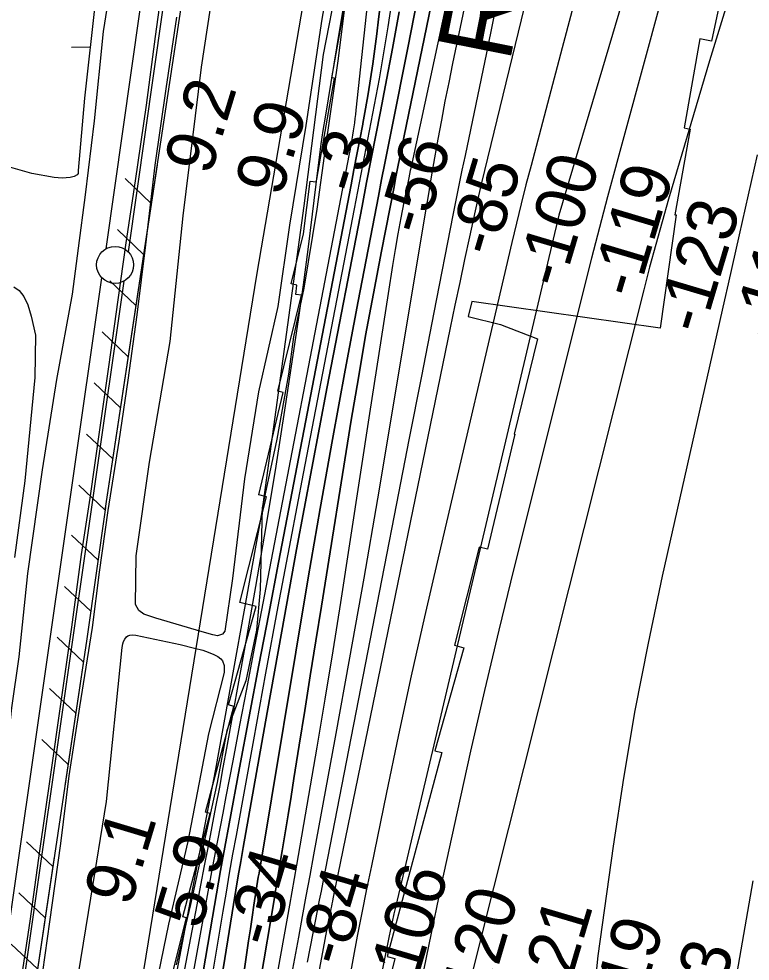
# Model space of a CAD drawing. Extents: x 3683613 to 3738215, y 469626 to 495384.
# Drawn here: x 3701179 to 3702169, y 479520 to 480796 of the extents above; entities that cross this region are included whole.
import ezdxf

# ---------------------------------------------------------------- set-up
doc = ezdxf.new("R2010")
doc.units = 0
for name, color, linetype in [('V-FLOD-BASE', 7, 'Continuous'), ('V-LEVE-TOET', 7, 'Continuous'), ('V-RIVR-EDGE', 7, 'Continuous'), ('V-RIVR-RANG', 7, 'Continuous'), ('V-RRAP-FSHR', 7, 'Continuous'), ('V-RRAP-RVMT', 7, 'Continuous'), ('V-RRAP-RVMT-IDEN', 7, 'Continuous'), ('V-SITE-VEGE', 7, 'Continuous'), ('V-SURV-LINE', 7, 'Continuous'), ('V-TOPO-DPTH', 7, 'Continuous'), ('V-TOPO-MAJR', 7, 'Continuous'), ('V-TOPO-MINR', 7, 'Continuous'), ('V-TOPO-WATR', 7, 'Continuous'), ('V-WETL-SWMP', 7, 'Continuous')]:
    doc.layers.add(name, color=color, linetype=linetype)

msp = doc.modelspace()

# ---------------------------------------------------------------- linework, layer by layer
at = {"layer": 'V-FLOD-BASE'}
msp.add_lwpolyline([(3701180.2, 479477.9), (3701194.5, 479573.7), (3701207.9, 479669), (3701222, 479769.3), (3701236.5, 479870.7), (3701251.2, 479971.9), (3701264, 480070), (3701275.9, 480146.6), (3701288.8, 480238.8), (3701301.1, 480324.2), (3701313.5, 480415.2), (3701324.6, 480492.1), (3701337, 480576.1), (3701351.9, 480678.7), (3701364.2, 480771.4), (3701376.3, 480860.7)], dxfattribs=at)
at = {"layer": 'V-LEVE-TOET'}
for points in [[(3701121.3, 479485), (3701137.7, 479604.2), (3701148.4, 479692.7), (3701157.7, 479758.9), (3701164.1, 479808), (3701169.8, 479862.6), (3701179.6, 479931.6), (3701191.4, 480044.6), (3701211.5, 480184.9), (3701230.7, 480307), (3701252, 480422.6), (3701260.2, 480485.2), (3701269.6, 480557), (3701281.8, 480657.3), (3701294, 480778.4), (3701313.2, 480900.7)], [(3701208.6, 479482.7), (3701221.2, 479572.9), (3701235.9, 479679.1), (3701247.6, 479770.7), (3701261.9, 479864), (3701278.8, 479971.6), (3701288.5, 480046.3), (3701300, 480129.7), (3701315.1, 480223.9), (3701327.3, 480306.4), (3701339.3, 480394.6), (3701351, 480489.3), (3701363.7, 480597.2), (3701378.7, 480700.6), (3701393.2, 480797.6)]]:
    msp.add_lwpolyline(points, dxfattribs=at)
at = {"layer": 'V-RIVR-EDGE'}
msp.add_lwpolyline([(3701622, 480825.2), (3701610.9, 480738.8), (3701594.4, 480623), (3701582.8, 480537.8), (3701565.1, 480431), (3701551.2, 480365), (3701544.4, 480314.5), (3701528.6, 480226.3), (3701508.6, 480133.3), (3701505.9, 480022.9), (3701501, 479967.7), (3701486.4, 479899.3), (3701461, 479832.1), (3701447.6, 479761.3), (3701432.4, 479691.7), (3701411.8, 479596.3), (3701392.4, 479514.7)], dxfattribs=at)
at = {"layer": 'V-RRAP-FSHR'}
for p, q in [((3701358.6, 480545.7), (3701323.2, 480579.4)), ((3701348.1, 480476.5), (3701312.8, 480510.1)), ((3701337.7, 480407.3), (3701302.3, 480440.9)), ((3701327.2, 480338), (3701291.9, 480371.7)), ((3701316.8, 480268.8), (3701281.4, 480302.5)), ((3701306.3, 480199.6), (3701270.9, 480233.3)), ((3701295.9, 480130.4), (3701260.5, 480164.1)), ((3701286.4, 480063.1), (3701250.7, 480096.4)), ((3701276.7, 479993.7), (3701240.9, 480027.1)), ((3701266.6, 479924.5), (3701231.2, 479958.1)), ((3701256.2, 479855.2), (3701220.8, 479888.9)), ((3701245.9, 479786), (3701210.5, 479819.6)), ((3701225.1, 479647.6), (3701189.7, 479681.2)), ((3701214.7, 479578.3), (3701179.3, 479612)), ((3701204.4, 479509.1), (3701169, 479542.7))]:
    msp.add_line(p, q, dxfattribs=at)
for points in [[(3701810.1, 483305.3), (3701737.4, 482845), (3701622, 482434.4), (3701596.4, 482302.9), (3701555, 481995.8), (3701532, 481804.5), (3701509, 481621.6), (3701469.4, 481255.9), (3701435.2, 481053.2), (3701296.3, 480133.1)], [(3701694.6, 481579.9), (3701501.3, 480451), (3701316.1, 479309.5), (3701244.1, 478830.2), (3701209.8, 478527.4), (3701127.5, 478317.7), (3700975.4, 478064.7), (3700849.2, 477767.3), (3700795.1, 477596.8), (3700754.6, 477321.3), (3700601.5, 476916.1), (3700241, 476175.5)], [(3701366.5, 480597.9), (3701296.3, 480133.1), (3701296.4, 480134), (3701271.4, 479956.2), (3701241.5, 479757.2)], [(3701296.4, 480134), (3701271.4, 479956.2), (3701142.6, 479096.9), (3701054.7, 478586.5), (3700925.4, 478175.9), (3700775.3, 477540.8), (3700732.4, 477433.8), (3700429.5, 476944.1)], [(3701227, 479660.3), (3701142.6, 479096.9), (3701127.6, 479010)]]:
    msp.add_lwpolyline(points, dxfattribs=at)
at = {"layer": 'V-RRAP-RVMT'}
for p, q in [((3702148.7, 480915.8), (3702116.7, 480765.2)), ((3701603, 480715.7), (3701630, 480868.7)), ((3702100.8, 480768.5), (3702079.6, 480647.9)), ((3702116.7, 480765.2), (3702100.8, 480768.5)), ((3701582.6, 480578.5), (3701606.7, 480715)), ((3701606.7, 480715), (3701603, 480715.7)), ((3702087.8, 480646.3), (3702067.3, 480530.2)), ((3702079.6, 480647.9), (3702087.8, 480646.3)), ((3701564.6, 480504.4), (3701573.7, 480575.7)), ((3701573.7, 480575.7), (3701581.8, 480574.7)), ((3701581.8, 480574.7), (3701582.8, 480578.4)), ((3701582.8, 480578.4), (3701582.6, 480578.5)), ((3702069.1, 480530), (3702047.5, 480376.8)), ((3702067.3, 480530.2), (3702069.1, 480530)), ((3701548, 480436.8), (3701564.6, 480504.4)), ((3701555.7, 480434.9), (3701548, 480436.8)), ((3701554.1, 480422.4), (3701555.7, 480434.9)), ((3701561.7, 480421.4), (3701554.1, 480422.4)), ((3701529.8, 480291.4), (3701561.7, 480421.4)), ((3701792.4, 480412.7), (3701787.5, 480392.5)), ((3702047.5, 480376.8), (3701792.4, 480412.7)), ((3701787.5, 480392.5), (3701831.4, 480381.8)), ((3701831.4, 480381.8), (3701881.2, 480362.1)), ((3701881.2, 480362.1), (3701849.7, 480233.3)), ((3701504.1, 480150.8), (3701537, 480289.7)), ((3701537, 480289.7), (3701529.8, 480291.4)), ((3701850.5, 480233.1), (3701813.7, 480077.6)), ((3701849.7, 480233.3), (3701850.5, 480233.1)), ((3701478.6, 480005.2), (3701514.7, 480148.2)), ((3701514.7, 480148.2), (3701504.1, 480150.8)), ((3701802.4, 480080.2), (3701768.8, 479947.4)), ((3701813.7, 480077.6), (3701802.4, 480080.2)), ((3701500.3, 479999.8), (3701478.6, 480005.2)), ((3701463, 479866.5), (3701500.3, 479999.8)), ((3701781.4, 479943.9), (3701742.4, 479804.6)), ((3701768.8, 479947.4), (3701781.4, 479943.9)), ((3701432, 479721.4), (3701470.1, 479864.5)), ((3701470.1, 479864.5), (3701463, 479866.5)), ((3701751.6, 479802.2), (3701710.4, 479647.3)), ((3701742.4, 479804.6), (3701751.6, 479802.2)), ((3701438.4, 479719.6), (3701432, 479721.4)), ((3701401.1, 479579.5), (3701438.4, 479719.6)), ((3701710.1, 479647.3), (3701677.7, 479525.7)), ((3701710.4, 479647.3), (3701710.1, 479647.3)), ((3701370.9, 479436.7), (3701406.1, 479578.1)), ((3701406.1, 479578.1), (3701401.1, 479579.5)), ((3701688.2, 479523.1), (3701652.2, 479379)), ((3701677.7, 479525.7), (3701688.2, 479523.1))]:
    msp.add_line(p, q, dxfattribs=at)
at = {"layer": 'V-SITE-VEGE'}
for points in [[(3701613.4, 480930.4), (3701589.5, 480795.3), (3701567.7, 480651.3), (3701545.4, 480516), (3701529.6, 480405.8), (3701503.7, 480290.5), (3701484.9, 480172.8), (3701468.5, 480037.8), (3701458, 479966.2), (3701455, 479962.3), (3701448.3, 479960), (3701441.9, 479961.3), (3701427.6, 479965.3), (3701364.8, 479984), (3701348.6, 479989.6), (3701341.8, 479994.3), (3701337, 480002.6), (3701338.1, 480068.2), (3701355.9, 480195.1), (3701384.2, 480358.7), (3701401.6, 480528.6), (3701426.6, 480729.9), (3701453.8, 480911.3)], [(3701253.2, 479461), (3701276.6, 479604.9), (3701298, 479735.7), (3701319.3, 479944.5), (3701320, 479949.1), (3701320.8, 479952.6), (3701322.6, 479955.7), (3701324.8, 479958.7), (3701326.7, 479960.1), (3701329.4, 479961.2), (3701332.6, 479961.5), (3701337.8, 479961), (3701397.8, 479948.2), (3701416.9, 479943.6), (3701428.1, 479940.7), (3701435.7, 479938.1), (3701443.1, 479934.9), (3701448.6, 479932.3), (3701452.7, 479929.1), (3701454.9, 479926.4), (3701457.1, 479919.9), (3701457, 479910.4), (3701435.8, 479827.2), (3701408, 479681.6), (3701381.8, 479569.8), (3701364.9, 479486.1)]]:
    msp.add_lwpolyline(points, dxfattribs=at)
at = {"layer": 'V-SURV-LINE'}
for points in [[(3701297.4, 480484.2), (3701560.1, 482333.7)], [(3701589.8, 482329.5), (3701327.1, 480480)], [(3701045.4, 478725.5), (3701291.8, 480444.7)], [(3701321.5, 480440.4), (3701075.1, 478721.3)]]:
    msp.add_lwpolyline(points, dxfattribs=at)
msp.add_circle((3701309.5, 480462.3), 25, dxfattribs=at)
at = {"layer": 'V-TOPO-DPTH'}
for points in [[(3701626.5, 480858.6), (3701613.2, 480781.3), (3701593.7, 480662.6), (3701590.8, 480644.5), (3701588.1, 480626.4), (3701585.7, 480608.3), (3701583.4, 480590.1), (3701576.2, 480530.9), (3701570.2, 480483.2), (3701563.9, 480435.4), (3701557.2, 480387.8), (3701550.2, 480340.2), (3701539.7, 480271.7), (3701526.9, 480189.9), (3701513.6, 480108.3), (3701499.7, 480026.7), (3701485.3, 479945.2), (3701460.5, 479808.1), (3701455.6, 479781.6), (3701450.7, 479755), (3701445.6, 479728.4), (3701440.5, 479701.9), (3701435.4, 479675.4), (3701430.2, 479648.8), (3701425.1, 479622.3), (3701420, 479595.8), (3701337.1, 479162.8)], [(3701484.3, 479505.9), (3701488, 479531.2), (3701490.3, 479547.2), (3701492.7, 479563.2), (3701495.1, 479579.2), (3701497.5, 479595.3), (3701500.7, 479615.7), (3701501.6, 479621.5), (3701502.5, 479627.3), (3701503.4, 479633.1), (3701504.4, 479638.9), (3701571.1, 480038.5), (3701587.1, 480132.3), (3701603.7, 480226.1), (3701620.9, 480319.8), (3701638.6, 480413.3), (3701666, 480555.3), (3701670.3, 480577.8), (3701674.7, 480600.3), (3701679.2, 480622.8), (3701683.6, 480645.3), (3701706.2, 480758.3), (3701721.5, 480837.4)], [(3701484.3, 479505.9), (3701488, 479531.2), (3701490.3, 479547.2), (3701492.7, 479563.2), (3701495.1, 479579.2), (3701497.5, 479595.3), (3701500.7, 479615.7), (3701501.6, 479621.5), (3701502.5, 479627.3), (3701503.4, 479633.1), (3701504.4, 479638.9), (3701571.1, 480038.5), (3701587.1, 480132.3), (3701603.7, 480226.1), (3701620.9, 480319.8), (3701638.6, 480413.3), (3701666, 480555.3), (3701670.3, 480577.8), (3701674.7, 480600.3), (3701679.2, 480622.8), (3701683.6, 480645.3), (3701706.2, 480758.3), (3701721.5, 480837.4)], [(3701668.6, 480815.7), (3701666.2, 480795.3), (3701663.7, 480775), (3701661, 480754.7), (3701658.2, 480734.4), (3701655.3, 480714.1), (3701652.1, 480693.9), (3701648.6, 480673.7), (3701644.8, 480653.6), (3701644.7, 480652.8), (3701640.7, 480632.2), (3701636.8, 480611.7), (3701632.8, 480591.2), (3701628.9, 480570.7), (3701530.8, 480059.6), (3701517.5, 479990.1), (3701504.3, 479920.5), (3701491.2, 479851), (3701478.1, 479781.4), (3701463.9, 479705.4), (3701458.1, 479673.8), (3701452.4, 479642.2), (3701446.8, 479610.6), (3701441.3, 479579), (3701419.2, 479449.7)], [(3701419.2, 479449.7), (3701441.3, 479579), (3701446.8, 479610.6), (3701452.4, 479642.2), (3701458.1, 479673.8), (3701463.9, 479705.4), (3701478.1, 479781.4), (3701491.2, 479851), (3701504.3, 479920.5), (3701517.5, 479990.1), (3701530.8, 480059.6), (3701628.9, 480570.7), (3701632.8, 480591.2), (3701636.8, 480611.7), (3701640.7, 480632.2), (3701644.7, 480652.8), (3701644.8, 480653.6), (3701648.6, 480673.7), (3701652.1, 480693.9), (3701655.3, 480714.1), (3701658.2, 480734.4), (3701661, 480754.7), (3701663.7, 480775), (3701666.2, 480795.3), (3701668.6, 480815.7)], [(3701449.2, 479467.3), (3701458, 479523.3), (3701469.9, 479596.5), (3701473, 479615.8), (3701476.3, 479635.1), (3701479.6, 479654.4), (3701483, 479673.7), (3701515.3, 479856.1), (3701535.1, 479966.5), (3701555.2, 480076.9), (3701575.9, 480187.2), (3701596.8, 480297.4), (3701643.8, 480541.9), (3701650, 480573.9), (3701656.2, 480605.9), (3701662.4, 480637.9), (3701668.7, 480669.9), (3701675.6, 480705.5), (3701685.1, 480755.3), (3701694, 480805.2)], [(3701694, 480805.2), (3701685.1, 480755.3), (3701675.6, 480705.5), (3701668.7, 480669.9), (3701662.4, 480637.9), (3701656.2, 480605.9), (3701650, 480573.9), (3701643.8, 480541.9), (3701596.8, 480297.4), (3701575.9, 480187.2), (3701555.2, 480076.9), (3701535.1, 479966.5), (3701515.3, 479856.1), (3701483, 479673.7), (3701479.6, 479654.4), (3701476.3, 479635.1), (3701473, 479615.8), (3701469.9, 479596.5), (3701458, 479523.3), (3701449.2, 479467.3)], [(3701737.4, 480814.5), (3701697.8, 480621.9), (3701695.1, 480608.4), (3701692.4, 480595), (3701689.7, 480581.6), (3701687.1, 480568.1), (3701670, 480480.9), (3701659.1, 480423.8), (3701648.7, 480366.7), (3701638.8, 480309.4), (3701629.3, 480252.1), (3701588.8, 480000.2), (3701581.3, 479953.1), (3701573.8, 479906.1), (3701566.3, 479859), (3701558.8, 479812), (3701551.7, 479766.9), (3701547.8, 479742.4), (3701543.8, 479717.9), (3701539.8, 479693.3), (3701535.7, 479668.8), (3701530, 479634.1), (3701528.8, 479626.9), (3701527.6, 479619.8), (3701526.4, 479612.7), (3701525.2, 479605.5), (3701467, 479261.5)], [(3701467, 479261.5), (3701525.2, 479605.5), (3701526.4, 479612.7), (3701527.6, 479619.8), (3701528.8, 479626.9), (3701530, 479634.1), (3701535.7, 479668.8), (3701539.8, 479693.3), (3701543.8, 479717.9), (3701547.8, 479742.4), (3701551.7, 479766.9), (3701558.8, 479812), (3701566.3, 479859), (3701573.8, 479906.1), (3701581.3, 479953.1), (3701588.8, 480000.2), (3701629.3, 480252.1), (3701638.8, 480309.4), (3701648.7, 480366.7), (3701659.1, 480423.8), (3701670, 480480.9), (3701687.1, 480568.1), (3701689.7, 480581.6), (3701692.4, 480595), (3701695.1, 480608.4), (3701697.8, 480621.9), (3701737.4, 480814.5)]]:
    msp.add_lwpolyline(points, dxfattribs=at)
at = {"layer": 'V-TOPO-MAJR'}
for points in [[(3702153.7, 481350.6), (3701910.1, 480529.5), (3701910.1, 480529.5)], [(3701800.4, 481014.8), (3701711.1, 480599.7), (3701710.1, 480594.8), (3701709.1, 480590), (3701708.1, 480585.1), (3701707.1, 480580.2), (3701700.5, 480547.3), (3701696.4, 480525.9), (3701692.4, 480504.4), (3701688.7, 480483), (3701685.2, 480461.5), (3701679.2, 480423.4), (3701672.9, 480382.8), (3701666.5, 480342.2), (3701660.2, 480301.6), (3701653.9, 480261), (3701614.5, 480005.2), (3701604.2, 479939.8), (3701593.6, 479874.5), (3701582.7, 479809.2), (3701571.5, 479743.9), (3701555, 479649.5), (3701551.8, 479631.5), (3701548.6, 479613.5), (3701545.5, 479595.5), (3701542.3, 479577.6), (3701513.3, 479415)], [(3701910.1, 480529.5), (3701689.4, 479594.3), (3701687, 479583.7), (3701684.6, 479573), (3701682.2, 479562.3), (3701680, 479551.6), (3701667.7, 479491.6)]]:
    msp.add_lwpolyline(points, dxfattribs=at)
at = {"layer": 'V-TOPO-MINR'}
for points in [[(3701942.1, 481135.9), (3701805.6, 480573.6), (3701804.2, 480567.7), (3701802.8, 480561.8), (3701801.5, 480555.9), (3701800.1, 480550), (3701789.3, 480500.3), (3701782.6, 480469.5), (3701776, 480438.7), (3701769.6, 480407.9), (3701763.2, 480377.1), (3701604.3, 479604.1), (3701603.6, 479600.7), (3701603, 479597.3), (3701602.3, 479594), (3701601.6, 479590.6), (3701598.1, 479573.1), (3701595.8, 479560.9), (3701593.4, 479548.8), (3701591.1, 479536.7), (3701588.9, 479524.5), (3701574.7, 479447.6)], [(3699911.1, 475180.8), (3700010.1, 475361), (3700100.2, 475592.8), (3700211, 475886.8), (3700368.1, 476293.1), (3700511.5, 476644.6), (3700757.8, 477156.6), (3700794.8, 477247.5), (3700948.6, 477732.3), (3701076.7, 478169.2), (3701195.6, 478587), (3701259.6, 478816.2), (3701288.9, 478956.9), (3701418.9, 479639), (3701445.8, 479779.7), (3701508.4, 480127.8), (3701565.5, 480542.5), (3701591.6, 480747.4), (3701650, 481045.5)], [(3702072.6, 480909.9), (3701976, 480554.5), (3701970.4, 480533.7), (3701965, 480513), (3701959.6, 480492.2), (3701954.3, 480471.4), (3701848.9, 480049.4), (3701828.9, 479967.7), (3701809.4, 479885.9), (3701790.7, 479803.9), (3701772.5, 479721.8), (3701751.1, 479622.9), (3701744.1, 479590.1), (3701737.2, 479557.3)], [(3701942.5, 480861.9), (3701914.8, 480756.2), (3701872.5, 480596.8), (3701865.7, 480570.8), (3701859.1, 480544.9), (3701852.7, 480518.8), (3701846.5, 480492.7), (3701746.8, 480065.7), (3701728.5, 479985.8), (3701710.5, 479905.9)], [(3701654, 480844.3), (3701635.5, 480671.7), (3701634.9, 480666.1), (3701634.2, 480660.5), (3701633.5, 480654.9), (3701632.8, 480649.3), (3701632, 480643.8), (3701631.1, 480638.2), (3701630.2, 480632.7), (3701629.2, 480627.1), (3701627.6, 480618.9), (3701627.2, 480616.8), (3701626.8, 480614.7), (3701626.4, 480612.7), (3701626, 480610.6), (3701496.5, 479936.1), (3701487.3, 479887.7), (3701478, 479839.3), (3701468.7, 479790.9), (3701459.5, 479742.5), (3701455.2, 479720.2), (3701448.1, 479682.9), (3701441.1, 479645.6), (3701434.2, 479608.3), (3701427.4, 479570.9), (3701382.4, 479322.7)], [(3701721.5, 480837.4), (3701706.2, 480758.3), (3701683.6, 480645.3), (3701679.2, 480622.8), (3701674.7, 480600.3), (3701670.3, 480577.8), (3701666, 480555.3), (3701638.6, 480413.3), (3701620.9, 480319.8), (3701603.7, 480226.1), (3701587.1, 480132.3), (3701571.1, 480038.5), (3701504.4, 479638.9), (3701503.4, 479633.1), (3701502.5, 479627.3), (3701501.6, 479621.5), (3701500.7, 479615.7), (3701497.5, 479595.3), (3701495.1, 479579.2), (3701492.7, 479563.2), (3701490.3, 479547.2), (3701488, 479531.2), (3701484.3, 479505.9)], [(3701830.4, 480839.3), (3701812.1, 480749.6), (3701783.2, 480610.6), (3701779, 480590.4), (3701774.9, 480570.2), (3701770.8, 480549.9), (3701766.8, 480529.7), (3701741, 480397.9), (3701724.2, 480311.8), (3701707.3, 480225.6), (3701690.5, 480139.5), (3701673.7, 480053.3), (3701590.6, 479626.6), (3701588.3, 479614.5), (3701585.9, 479602.4), (3701583.6, 479590.3), (3701581.2, 479578.2), (3701569.6, 479518.1)], [(3702144.8, 480839), (3702114.2, 480738.5), (3702058.7, 480551.2), (3702049.9, 480520.7), (3702041.3, 480490), (3702033.1, 480459.3), (3702025.1, 480428.5), (3701801.2, 479538.2), (3701622.5, 478819.7)], [(3701684.1, 480820.3), (3701678.7, 480784.9), (3701673, 480749.6), (3701666.8, 480714.3), (3701660.2, 480679.1), (3701653.4, 480643.9), (3701646.6, 480608.8), (3701639.8, 480573.6), (3701633, 480538.4), (3701564.2, 480179.9), (3701547, 480089.8), (3701530, 479999.7), (3701513.3, 479909.5), (3701496.7, 479819.3), (3701473.2, 479689.9), (3701468.6, 479664.4), (3701464.1, 479638.8), (3701459.7, 479613.1), (3701455.4, 479587.5), (3701438.7, 479487.2)], [(3701668.6, 480815.7), (3701666.2, 480795.3), (3701663.7, 480775), (3701661, 480754.7), (3701658.2, 480734.4), (3701655.3, 480714.1), (3701652.1, 480693.9), (3701648.6, 480673.7), (3701644.8, 480653.6), (3701644.7, 480652.8), (3701640.7, 480632.2), (3701636.8, 480611.7), (3701632.8, 480591.2), (3701628.9, 480570.7), (3701530.8, 480059.6), (3701517.5, 479990.1), (3701504.3, 479920.5), (3701491.2, 479851), (3701478.1, 479781.4), (3701463.9, 479705.4), (3701458.1, 479673.8), (3701452.4, 479642.2), (3701446.8, 479610.6), (3701441.3, 479579), (3701419.2, 479449.7)], [(3701694, 480805.2), (3701685.1, 480755.3), (3701675.6, 480705.5), (3701668.7, 480669.9), (3701662.4, 480637.9), (3701656.2, 480605.9), (3701650, 480573.9), (3701643.8, 480541.9), (3701596.8, 480297.4), (3701575.9, 480187.2), (3701555.2, 480076.9), (3701535.1, 479966.5), (3701515.3, 479856.1), (3701483, 479673.7), (3701479.6, 479654.4), (3701476.3, 479635.1), (3701473, 479615.8), (3701469.9, 479596.5), (3701458, 479523.3), (3701449.2, 479467.3)], [(3701737.4, 480814.5), (3701697.8, 480621.9), (3701695.1, 480608.4), (3701692.4, 480595), (3701689.7, 480581.6), (3701687.1, 480568.1), (3701670, 480480.9), (3701659.1, 480423.8), (3701648.7, 480366.7), (3701638.8, 480309.4), (3701629.3, 480252.1), (3701588.8, 480000.2), (3701581.3, 479953.1), (3701573.8, 479906.1), (3701566.3, 479859), (3701558.8, 479812), (3701551.7, 479766.9), (3701547.8, 479742.4), (3701543.8, 479717.9), (3701539.8, 479693.3), (3701535.7, 479668.8), (3701530, 479634.1), (3701528.8, 479626.9), (3701527.6, 479619.8), (3701526.4, 479612.7), (3701525.2, 479605.5), (3701467, 479261.5)], [(3701782.1, 480809.8), (3701766.4, 480735), (3701761.1, 480709.5), (3701756, 480683.9), (3701751.2, 480658.3), (3701746.5, 480632.7), (3701742, 480607.1), (3701737.5, 480581.4), (3701733.2, 480555.8), (3701728.8, 480530.1), (3701682.8, 480253.6), (3701664.6, 480145.8), (3701646, 480038.1), (3701626.9, 479930.4), (3701607.4, 479822.8), (3701578.2, 479663.4), (3701573, 479635.6), (3701567.9, 479607.8), (3701562.8, 479579.9), (3701557.6, 479552.1), (3701541.4, 479465.5)], [(3701967.7, 479366.8), (3701967.9, 479377.2), (3701968, 479387.7), (3701967.7, 479398.1), (3701967.2, 479408.5), (3701966.4, 479418.9), (3701965.4, 479429.3), (3701962.5, 479455.7), (3701961.2, 479473.5), (3701960.8, 479491.2), (3701961.7, 479509), (3701963.5, 479526.7), (3701984.1, 479675.5), (3701998, 479767.4), (3702013.5, 479859), (3702031.3, 479950.2), (3702050.6, 480041.1), (3702134.8, 480414.9), (3702139.8, 480436.9), (3702144.8, 480458.9), (3702149.7, 480480.9), (3702154.6, 480502.9), (3702179, 480611.4)], [(3701710.5, 479905.9), (3701693.3, 479825.9), (3701676.4, 479745.7), (3701656.4, 479648.8), (3701649.9, 479617), (3701643.6, 479585.2), (3701637.4, 479553.4), (3701631.5, 479521.6), (3701600.5, 479354.1)], [(3702147.8, 479483.2), (3702173.3, 479628.4)], [(3701737.2, 479557.3), (3701730.5, 479524.5), (3701723.8, 479491.6)]]:
    msp.add_lwpolyline(points, dxfattribs=at)
at = {"layer": 'V-TOPO-WATR'}
msp.add_lwpolyline([(3701626.5, 480858.6), (3701613.2, 480781.3), (3701593.7, 480662.6), (3701590.8, 480644.5), (3701588.1, 480626.4), (3701585.7, 480608.3), (3701583.4, 480590.1), (3701576.2, 480530.9), (3701570.2, 480483.2), (3701563.9, 480435.4), (3701557.2, 480387.8), (3701550.2, 480340.2), (3701539.7, 480271.7), (3701526.9, 480189.9), (3701513.6, 480108.3), (3701499.7, 480026.7), (3701485.3, 479945.2), (3701460.5, 479808.1), (3701455.6, 479781.6), (3701450.7, 479755), (3701445.6, 479728.4), (3701440.5, 479701.9), (3701435.4, 479675.4), (3701430.2, 479648.8), (3701425.1, 479622.3), (3701420, 479595.8), (3701337.1, 479162.8)], dxfattribs=at)
at = {"layer": 'V-WETL-SWMP'}
msp.add_line((3701250.5, 480757.2), (3701275.9, 480757.5), dxfattribs=at)
for points in [[(3701283.1, 480822.3), (3701268.2, 480687.9), (3701259.7, 480590.1), (3701259.7, 480585.9), (3701258.3, 480584.5), (3701254.2, 480582), (3701248.9, 480580.5), (3701238, 480579.8), (3701227.1, 480580.8), (3701196.9, 480586), (3701041.5, 480630.5), (3700905.5, 480680.7), (3700885.8, 480689.1), (3700872.1, 480696.1), (3700861.6, 480703.8), (3700852.9, 480712.1), (3700847.8, 480720.1), (3700845.7, 480728.4), (3700845.6, 480737.1), (3700851.2, 480753.6), (3700902.2, 480871.2)], [(3701172.7, 480432.7), (3701179.7, 480427.5), (3701186, 480419.5), (3701191.4, 480408.1), (3701196.1, 480393.1), (3701201.7, 480367.2), (3701201.1, 480310), (3701187.6, 480169.8), (3701173.6, 480066.1)]]:
    msp.add_lwpolyline(points, dxfattribs=at)

# ---------------------------------------------------------------- texts
at = {"layer": 'V-RIVR-RANG'}
for s, rotation, p in [('9.2', 73.1183, (3701438.5, 480582)), ('9.9', 73.1183, (3701534.2, 480553)), ('-3', 73.1183, (3701639.6, 480556)), ('-56', 73.3975, (3701727.7, 480500.4)), ('-85', 73.3975, (3701823.3, 480471.1)), ('-100', 73.3975, (3701914.9, 480428.4)), ('-119', 73.3975, (3702015.2, 480414.8)), ('-123', 73.3975, (3702105.1, 480366.5)), ('-117', 73.3975, (3702206.6, 480356.9)), ('9.1', 73.2483, (3701330.2, 479591.9)), ('5.9', 73.2483, (3701425.2, 479560.8)), ('-34', 73.5343, (3701522.6, 479536)), ('-106', 73.5343, (3701710.6, 479466.5)), ('-84', 73.5343, (3701619.2, 479510)), ('-120', 73.5343, (3701805.6, 479435.1)), ('-121', 73.5343, (3701905.7, 479420.7)), ('-119', 73.5343, (3702002.4, 479395.1)), ('-113', 73.5343, (3702097.2, 479363.3))]:
    msp.add_text(s, height=67, rotation=rotation, dxfattribs=at).set_placement(p)
at = {"layer": 'V-RRAP-RVMT-IDEN'}
msp.add_text('REVET', height=100, rotation=78.831, dxfattribs=at).set_placement((3701843.6, 480735.2))

doc.saveas('drawing.dxf')
